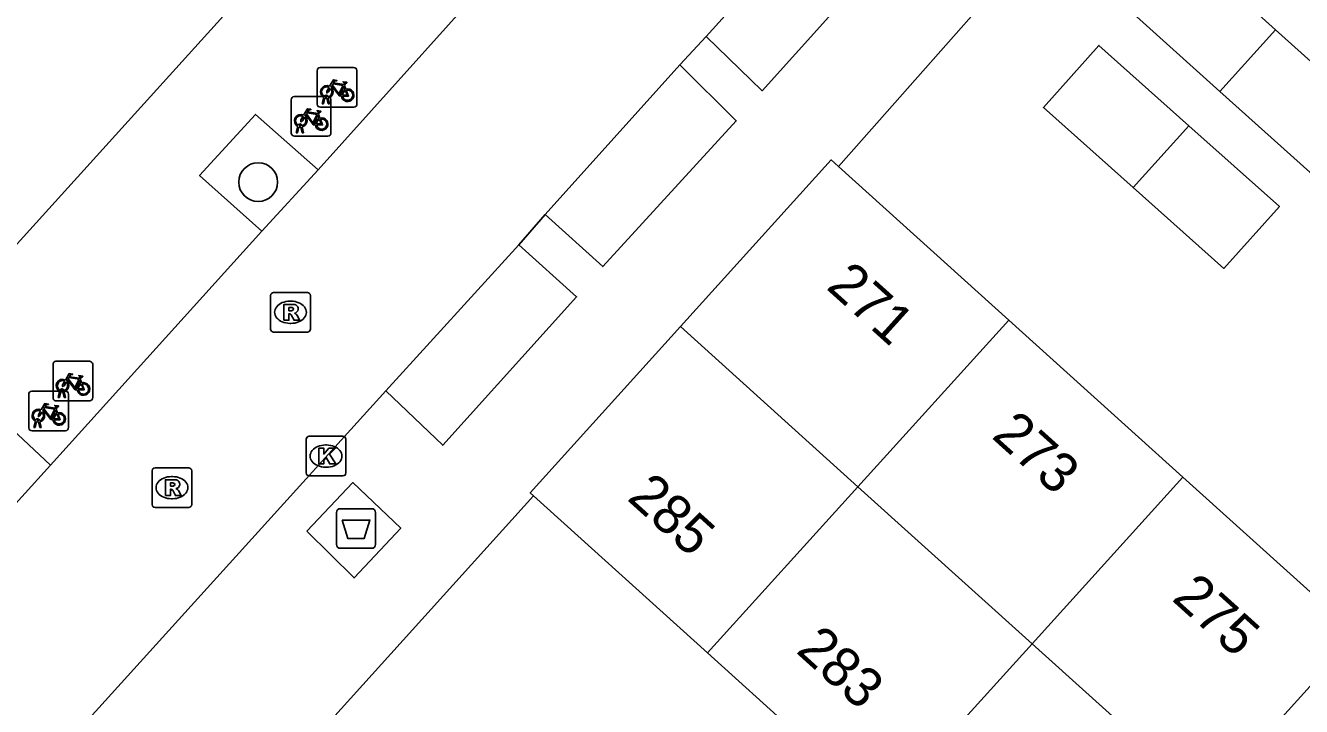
# Model space of a CAD drawing. Extents: x 161772 to 163123, y 383092 to 383917.
# Drawn here: x 162073.6 to 162105.76, y 383195.91 to 383213.09 of the extents above; entities that cross this region are included whole.
import ezdxf

# ---------------------------------------------------------------- set-up
doc = ezdxf.new("R2010")
doc.units = 0
for name, color, linetype in [('IMGEO_Afval_apart_plaats', 7, 'Continuous'), ('IMGEO_Boom', 7, 'Continuous'), ('IMGEO_Fietsenrek', 7, 'Continuous'), ('IMGEO_Kolk', 7, 'Continuous'), ('IMGEO_Pand', 7, 'Continuous'), ('IMGEO_Pand_nummerreeks', 7, 'Continuous'), ('IMGEO_Rijbaan_lokaal_open', 7, 'Continuous'), ('IMGEO_Rioolput', 7, 'Continuous'), ('IMGEO_Voetpad_gesloten', 7, 'Continuous'), ('IMGEO_Voetpad_open', 7, 'Continuous')]:
    doc.layers.add(name, color=color, linetype=linetype)

msp = doc.modelspace()

# ---------------------------------------------------------------- linework, layer by layer
at = {"layer": 'IMGEO_Afval_apart_plaats'}
for p, q in [((162081.531, 383200.9), (162082.321, 383200.9)), ((162082.321, 383200.9), (162081.531, 383200.9)), ((162081.431, 383200), (162081.431, 383200.8)), ((162081.431, 383200.8), (162081.431, 383200)), ((162082.421, 383200.8), (162082.421, 383200)), ((162082.421, 383200), (162082.421, 383200.8)), ((162082.321, 383199.9), (162081.531, 383199.9)), ((162081.531, 383199.9), (162082.321, 383199.9))]:
    msp.add_line(p, q, dxfattribs=at)
msp.add_lwpolyline([(162081.574, 383200.614), (162082.278, 383200.614), (162082.129, 383200.144), (162081.723, 383200.144), (162081.574, 383200.614)], dxfattribs=at)
for centre, start, end in [((162081.531, 383200.8), 90, 180), ((162081.531, 383200.8), 90, 180), ((162082.321, 383200.8), 0, 90), ((162082.321, 383200.8), 360, 90), ((162081.531, 383200), 180, 270), ((162081.531, 383200), 180, 270), ((162082.321, 383200), 270, 0), ((162082.321, 383200), 270, 0)]:
    msp.add_arc(centre, 0.1, start, end, dxfattribs=at)
at = {"layer": 'IMGEO_Boom'}
msp.add_circle((162079.461, 383209.138), 0.489, dxfattribs=at)
at = {"layer": 'IMGEO_Fietsenrek'}
for p, q in [((162080.948, 383211.104), (162080.948, 383211.945)), ((162080.948, 383211.945), (162080.948, 383211.104)), ((162081.023, 383212.029), (162081.864, 383212.029)), ((162081.864, 383212.029), (162081.023, 383212.029)), ((162081.948, 383211.954), (162081.948, 383211.113)), ((162081.948, 383211.113), (162081.948, 383211.954)), ((162081.635, 383211.578), (162081.671, 383211.483)), ((162080.293, 383210.375), (162080.293, 383211.216)), ((162080.293, 383211.216), (162080.293, 383210.375)), ((162080.368, 383211.3), (162081.209, 383211.3)), ((162081.209, 383211.3), (162080.368, 383211.3)), ((162081.075, 383211.113), (162081.114, 383211.273)), ((162081.109, 383211.113), (162081.075, 383211.113)), ((162081.144, 383211.261), (162081.109, 383211.113)), ((162081.186, 383211.285), (162081.185, 383211.289)), ((162081.227, 383211.113), (162081.193, 383211.255)), ((162081.217, 383211.296), (162081.218, 383211.289)), ((162081.225, 383211.259), (162081.26, 383211.113)), ((162081.26, 383211.113), (162081.227, 383211.113)), ((162081.293, 383211.225), (162081.293, 383210.384)), ((162081.293, 383210.384), (162081.293, 383211.225)), ((162080.98, 383210.849), (162081.016, 383210.754)), ((162081.873, 383211.029), (162081.032, 383211.029)), ((162081.032, 383211.029), (162081.873, 383211.029)), ((162080.42, 383210.384), (162080.459, 383210.544)), ((162080.489, 383210.532), (162080.454, 383210.384)), ((162080.531, 383210.556), (162080.53, 383210.56)), ((162080.572, 383210.384), (162080.538, 383210.526)), ((162080.562, 383210.567), (162080.563, 383210.56)), ((162080.57, 383210.53), (162080.605, 383210.384)), ((162081.218, 383210.3), (162080.377, 383210.3)), ((162080.377, 383210.3), (162081.218, 383210.3)), ((162080.454, 383210.384), (162080.42, 383210.384)), ((162080.605, 383210.384), (162080.572, 383210.384)), ((162074.289, 383203.694), (162074.289, 383204.535)), ((162074.289, 383204.535), (162074.289, 383203.694)), ((162074.364, 383204.619), (162075.205, 383204.619)), ((162075.205, 383204.619), (162074.364, 383204.619)), ((162075.289, 383204.544), (162075.289, 383203.703)), ((162075.289, 383203.703), (162075.289, 383204.544)), ((162074.976, 383204.168), (162075.012, 383204.073)), ((162073.678, 383202.939), (162073.678, 383203.78)), ((162073.678, 383203.78), (162073.678, 383202.939)), ((162073.753, 383203.864), (162074.594, 383203.864)), ((162074.594, 383203.864), (162073.753, 383203.864)), ((162074.416, 383203.703), (162074.455, 383203.863)), ((162074.45, 383203.703), (162074.416, 383203.703)), ((162074.485, 383203.851), (162074.45, 383203.703)), ((162074.527, 383203.875), (162074.526, 383203.879)), ((162074.568, 383203.703), (162074.534, 383203.845)), ((162074.558, 383203.886), (162074.559, 383203.879)), ((162074.566, 383203.849), (162074.601, 383203.703)), ((162074.601, 383203.703), (162074.568, 383203.703)), ((162074.678, 383203.789), (162074.678, 383202.948)), ((162074.678, 383202.948), (162074.678, 383203.789)), ((162074.365, 383203.413), (162074.401, 383203.318)), ((162075.214, 383203.619), (162074.373, 383203.619)), ((162074.373, 383203.619), (162075.214, 383203.619)), ((162073.805, 383202.948), (162073.844, 383203.108)), ((162073.874, 383203.096), (162073.839, 383202.948)), ((162073.916, 383203.12), (162073.915, 383203.124)), ((162073.957, 383202.948), (162073.923, 383203.09)), ((162073.947, 383203.131), (162073.948, 383203.124)), ((162073.955, 383203.094), (162073.99, 383202.948)), ((162074.603, 383202.864), (162073.762, 383202.864)), ((162073.762, 383202.864), (162074.603, 383202.864)), ((162073.839, 383202.948), (162073.805, 383202.948)), ((162073.99, 383202.948), (162073.957, 383202.948))]:
    msp.add_line(p, q, dxfattribs=at)
for points in [[(162081.282, 383211.503), (162081.23, 383211.413), (162081.19, 383211.388), (162081.191, 383211.435), (162081.246, 383211.529)], [(162081.261, 383211.555), (162081.356, 383211.719), (162081.442, 383211.705), (162081.444, 383211.696), (162081.388, 383211.685), (162081.361, 383211.64), (162081.617, 383211.599)], [(162081.557, 383211.311), (162081.507, 383211.311), (162081.316, 383211.562), (162081.297, 383211.53)], [(162081.604, 383211.574), (162081.347, 383211.615), (162081.33, 383211.586), (162081.497, 383211.366), (162081.604, 383211.574)], [(162081.652, 383211.476), (162081.622, 383211.553), (162081.513, 383211.335), (162081.556, 383211.335)], [(162081.586, 383211.335), (162081.706, 383211.334), (162081.662, 383211.448)], [(162081.682, 383211.455), (162081.737, 383211.31), (162081.587, 383211.31)], [(162081.617, 383211.599), (162081.642, 383211.648), (162081.636, 383211.652), (162081.613, 383211.656), (162081.601, 383211.663), (162081.6, 383211.666), (162081.602, 383211.671), (162081.697, 383211.656), (162081.699, 383211.646), (162081.689, 383211.633), (162081.677, 383211.627), (162081.663, 383211.633), (162081.635, 383211.578)], [(162080.627, 383210.774), (162080.575, 383210.684), (162080.535, 383210.659), (162080.536, 383210.706), (162080.591, 383210.8)], [(162080.606, 383210.826), (162080.701, 383210.99), (162080.787, 383210.976), (162080.789, 383210.967), (162080.733, 383210.956), (162080.706, 383210.911), (162080.962, 383210.87)], [(162080.902, 383210.582), (162080.852, 383210.582), (162080.661, 383210.833), (162080.642, 383210.801)], [(162080.949, 383210.845), (162080.692, 383210.886), (162080.675, 383210.857), (162080.842, 383210.637), (162080.949, 383210.845)], [(162080.997, 383210.747), (162080.967, 383210.824), (162080.858, 383210.606), (162080.901, 383210.606)], [(162080.962, 383210.87), (162080.987, 383210.919), (162080.981, 383210.923), (162080.958, 383210.927), (162080.946, 383210.934), (162080.945, 383210.937), (162080.947, 383210.942), (162081.042, 383210.927), (162081.044, 383210.917), (162081.034, 383210.904), (162081.022, 383210.898), (162081.008, 383210.904), (162080.98, 383210.849)], [(162080.931, 383210.606), (162081.051, 383210.605), (162081.007, 383210.719)], [(162081.027, 383210.726), (162081.082, 383210.581), (162080.932, 383210.581)], [(162074.623, 383204.093), (162074.571, 383204.003), (162074.531, 383203.978), (162074.532, 383204.025), (162074.587, 383204.119)], [(162074.602, 383204.145), (162074.697, 383204.309), (162074.783, 383204.295), (162074.785, 383204.286), (162074.729, 383204.275), (162074.702, 383204.23), (162074.958, 383204.189)], [(162074.898, 383203.901), (162074.848, 383203.901), (162074.657, 383204.152), (162074.638, 383204.12)], [(162074.945, 383204.164), (162074.688, 383204.205), (162074.671, 383204.176), (162074.838, 383203.956), (162074.945, 383204.164)], [(162074.993, 383204.066), (162074.963, 383204.143), (162074.854, 383203.925), (162074.897, 383203.925)], [(162074.927, 383203.925), (162075.047, 383203.924), (162075.003, 383204.038)], [(162075.023, 383204.045), (162075.078, 383203.9), (162074.928, 383203.9)], [(162074.958, 383204.189), (162074.983, 383204.238), (162074.977, 383204.242), (162074.954, 383204.246), (162074.942, 383204.253), (162074.941, 383204.256), (162074.943, 383204.261), (162075.038, 383204.246), (162075.04, 383204.236), (162075.03, 383204.223), (162075.018, 383204.217), (162075.004, 383204.223), (162074.976, 383204.168)], [(162073.991, 383203.39), (162074.086, 383203.554), (162074.172, 383203.54), (162074.174, 383203.531), (162074.118, 383203.52), (162074.091, 383203.475), (162074.347, 383203.434)], [(162074.287, 383203.146), (162074.237, 383203.146), (162074.046, 383203.397), (162074.027, 383203.365)], [(162074.334, 383203.409), (162074.077, 383203.45), (162074.06, 383203.421), (162074.227, 383203.201), (162074.334, 383203.409)], [(162074.382, 383203.311), (162074.352, 383203.388), (162074.243, 383203.17), (162074.286, 383203.17)], [(162074.347, 383203.434), (162074.372, 383203.483), (162074.366, 383203.487), (162074.343, 383203.491), (162074.331, 383203.498), (162074.33, 383203.501), (162074.332, 383203.506), (162074.427, 383203.491), (162074.429, 383203.481), (162074.419, 383203.468), (162074.407, 383203.462), (162074.393, 383203.468), (162074.365, 383203.413)], [(162074.012, 383203.338), (162073.96, 383203.248), (162073.92, 383203.223), (162073.921, 383203.27), (162073.976, 383203.364)], [(162074.316, 383203.17), (162074.436, 383203.169), (162074.392, 383203.283)], [(162074.412, 383203.29), (162074.467, 383203.145), (162074.317, 383203.145)]]:
    msp.add_lwpolyline(points, dxfattribs=at)
for centre, radius, start, end in [((162081.026, 383211.951), 0.0779, 92.4484, 184.2845), ((162081.026, 383211.951), 0.0779, 92.4484, 184.2845), ((162081.87, 383211.951), 0.0779, 2.4484, 94.2845), ((162081.87, 383211.951), 0.0779, 2.4484, 94.2845), ((162081.188, 383211.414), 0.159, 62.6766, 242.1369), ((162081.188, 383211.414), 0.129, 63.3192, 238.903), ((162081.188, 383211.414), 0.129, 283.6043, 43.4302), ((162081.188, 383211.414), 0.159, 283.5766, 46.6042), ((162081.715, 383211.33), 0.159, 113.3408, 178.3217), ((162081.715, 383211.33), 0.159, 187.0065, 105.7708), ((162081.715, 383211.33), 0.129, 113.923, 177.9556), ((162081.715, 383211.33), 0.129, 188.6715, 104.5883), ((162080.371, 383211.222), 0.0779, 92.4484, 184.2845), ((162080.371, 383211.222), 0.0779, 92.4484, 184.2845), ((162081.026, 383211.107), 0.0779, 182.4484, 274.2845), ((162081.026, 383211.107), 0.0779, 182.4484, 274.2845), ((162081.168, 383211.285), 0.0499, 12.8025, 158.6934), ((162081.188, 383211.414), 0.159, 253.9967, 271.7867), ((162081.168, 383211.285), 0.0174, 12.8025, 163.4502), ((162081.188, 383211.414), 0.129, 253.415, 269.0204), ((162081.215, 383211.222), 0.0779, 2.4484, 94.2845), ((162081.215, 383211.222), 0.0779, 2.4484, 94.2845), ((162081.87, 383211.107), 0.0779, 272.4484, 4.2845), ((162081.87, 383211.107), 0.0779, 272.4484, 4.2845), ((162080.533, 383210.685), 0.159, 62.6766, 242.1369), ((162080.533, 383210.685), 0.129, 63.3192, 238.903), ((162080.533, 383210.685), 0.129, 283.6043, 43.4302), ((162080.533, 383210.685), 0.159, 283.5766, 46.6042), ((162080.513, 383210.556), 0.0499, 12.8025, 158.6934), ((162080.533, 383210.685), 0.159, 253.9967, 271.7867), ((162080.513, 383210.556), 0.0174, 12.8025, 163.4502), ((162080.533, 383210.685), 0.129, 253.415, 269.0204), ((162081.06, 383210.601), 0.159, 113.3408, 178.3217), ((162081.06, 383210.601), 0.159, 187.0065, 105.7708), ((162081.06, 383210.601), 0.129, 113.923, 177.9556), ((162081.06, 383210.601), 0.129, 188.6715, 104.5883), ((162080.371, 383210.378), 0.0779, 182.4484, 274.2845), ((162080.371, 383210.378), 0.0779, 182.4484, 274.2845), ((162081.215, 383210.378), 0.0779, 272.4484, 4.2845), ((162081.215, 383210.378), 0.0779, 272.4484, 4.2845), ((162074.367, 383204.541), 0.0779, 92.4484, 184.2845), ((162074.367, 383204.541), 0.0779, 92.4484, 184.2845), ((162075.211, 383204.541), 0.0779, 2.4484, 94.2845), ((162075.211, 383204.541), 0.0779, 2.4484, 94.2845), ((162074.529, 383204.004), 0.159, 62.6766, 242.1369), ((162074.529, 383204.004), 0.129, 63.3192, 238.903), ((162074.529, 383204.004), 0.129, 283.6043, 43.4302), ((162074.529, 383204.004), 0.159, 283.5766, 46.6042), ((162075.056, 383203.92), 0.159, 113.3408, 178.3217), ((162075.056, 383203.92), 0.159, 187.0065, 105.7708), ((162075.056, 383203.92), 0.129, 113.923, 177.9556), ((162075.056, 383203.92), 0.129, 188.6715, 104.5883), ((162073.756, 383203.786), 0.0779, 92.4484, 184.2845), ((162073.756, 383203.786), 0.0779, 92.4484, 184.2845), ((162074.509, 383203.875), 0.0499, 12.8025, 158.6934), ((162074.529, 383204.004), 0.159, 253.9967, 271.7867), ((162074.509, 383203.875), 0.0174, 12.8025, 163.4502), ((162074.529, 383204.004), 0.129, 253.415, 269.0204), ((162074.6, 383203.786), 0.0779, 2.4484, 94.2845), ((162074.6, 383203.786), 0.0779, 2.4484, 94.2845), ((162075.211, 383203.697), 0.0779, 272.4484, 4.2845), ((162075.211, 383203.697), 0.0779, 272.4484, 4.2845), ((162073.918, 383203.249), 0.159, 62.6766, 242.1369), ((162073.918, 383203.249), 0.129, 63.3192, 238.903), ((162074.367, 383203.697), 0.0779, 182.4484, 274.2845), ((162074.367, 383203.697), 0.0779, 182.4484, 274.2845), ((162073.898, 383203.12), 0.0499, 12.8025, 158.6934), ((162073.918, 383203.249), 0.159, 253.9967, 271.7867), ((162073.898, 383203.12), 0.0174, 12.8025, 163.4502), ((162073.918, 383203.249), 0.129, 253.415, 269.0204), ((162073.918, 383203.249), 0.129, 283.6043, 43.4302), ((162073.918, 383203.249), 0.159, 283.5766, 46.6042), ((162074.445, 383203.165), 0.159, 113.3408, 178.3217), ((162074.445, 383203.165), 0.159, 187.0065, 105.7708), ((162074.445, 383203.165), 0.129, 113.923, 177.9556), ((162074.445, 383203.165), 0.129, 188.6715, 104.5883), ((162073.756, 383202.942), 0.0779, 182.4484, 274.2845), ((162073.756, 383202.942), 0.0779, 182.4484, 274.2845), ((162074.6, 383202.942), 0.0779, 272.4484, 4.2845), ((162074.6, 383202.942), 0.0779, 272.4484, 4.2845)]:
    msp.add_arc(centre, radius, start, end, dxfattribs=at)
at = {"layer": 'IMGEO_Kolk'}
for p, q in [((162080.67, 383201.801), (162080.67, 383202.653)), ((162080.745, 383202.727), (162081.597, 383202.727)), ((162081.158, 383202.507), (162081.183, 383202.507)), ((162081.671, 383202.653), (162081.671, 383201.801)), ((162081.181, 383201.947), (162081.156, 383201.947)), ((162081.597, 383201.727), (162080.745, 383201.727))]:
    msp.add_line(p, q, dxfattribs=at)
for points in [[(162080.67, 383201.801), (162080.67, 383202.653)], [(162080.745, 383202.727), (162081.597, 383202.727)], [(162080.991, 383202.427), (162081.114, 383202.427), (162081.114, 383202.276), (162081.244, 383202.427), (162081.408, 383202.427), (162081.262, 383202.276), (162081.415, 383202.027), (162081.263, 383202.027), (162081.178, 383202.191), (162081.114, 383202.124), (162081.114, 383202.027), (162080.991, 383202.027), (162080.991, 383202.427)], [(162081.671, 383202.653), (162081.671, 383201.801)], [(162081.597, 383201.727), (162080.745, 383201.727)]]:
    msp.add_lwpolyline(points, dxfattribs=at)
for centre, start, end in [((162080.747, 383202.651), 91.552, 178.448), ((162080.747, 383202.651), 91.552, 178.448), ((162081.595, 383202.651), 1.552, 88.448), ((162081.595, 383202.651), 1.552, 88.448), ((162080.747, 383201.803), 181.552, 268.448), ((162080.747, 383201.803), 181.552, 268.448), ((162081.595, 383201.803), 271.552, 358.448), ((162081.595, 383201.803), 271.552, 358.448)]:
    msp.add_arc(centre, 0.0765, start, end, dxfattribs=at)
for centre, major_axis, ratio, start_param, end_param in [((162081.157, 383202.227), (-0.387, 0.002), 0.722429, 4.712389, 7.853982), ((162081.182, 383202.227), (-0.39, 0.002), 0.717154, 1.570796, 4.712389)]:
    msp.add_ellipse(centre, major_axis=major_axis, ratio=ratio, start_param=start_param, end_param=end_param, dxfattribs=at)
at = {"layer": 'IMGEO_Pand'}
for points in [[(162103.698, 383211.427), (162101.431, 383213.469), (162102.822, 383215.036), (162105.1, 383212.984)], [(162105.1, 383212.984), (162107.367, 383210.943), (162105.964, 383209.385), (162103.698, 383211.427)], [(162105.1, 383212.984), (162103.698, 383211.427)], [(162101.515, 383209.005), (162099.254, 383211.024), (162100.651, 383212.588), (162102.918, 383210.562)], [(162102.918, 383210.562), (162105.2, 383208.524), (162103.804, 383206.961), (162101.515, 383209.005)], [(162102.918, 383210.562), (162101.515, 383209.005)], [(162094.087, 383209.529), (162093.9, 383209.698), (162090.104, 383205.493)], [(162094.087, 383209.529), (162098.378, 383205.658)], [(162094.578, 383201.455), (162098.378, 383205.658)], [(162098.378, 383205.658), (162102.77, 383201.695)], [(162090.104, 383205.493), (162086.317, 383201.299), (162086.397, 383201.227)], [(162094.578, 383201.455), (162090.104, 383205.493)], [(162090.785, 383197.26), (162094.578, 383201.455)], [(162098.969, 383197.491), (162094.578, 383201.455)], [(162098.969, 383197.491), (162102.77, 383201.695)], [(162102.77, 383201.695), (162107.162, 383197.733)], [(162090.785, 383197.26), (162086.397, 383201.227)], [(162103.361, 383193.528), (162107.162, 383197.733)], [(162095.174, 383193.293), (162098.969, 383197.491)], [(162103.361, 383193.528), (162098.969, 383197.491)], [(162095.174, 383193.293), (162090.785, 383197.26)]]:
    msp.add_lwpolyline(points, dxfattribs=at)
at = {"layer": 'IMGEO_Rijbaan_lokaal_open'}
for points in [[(162068.652, 383202.355), (162096.663, 383233.336), (162100.456, 383238.097), (162111.993, 383252.292), (162112.228, 383252.578), (162118.339, 383260.004), (162114.439, 383263.213), (162114.338, 383263.296), (162092.847, 383280.981), (162088.992, 383283.992)], [(162090.753, 383212.81), (162094.09, 383216.514)], [(162086.275, 383215.36), (162080.969, 383209.451)], [(162090.088, 383212.094), (162090.753, 383212.81)], [(162086.694, 383208.318), (162090.088, 383212.094)], [(162079.552, 383207.898), (162077.982, 383209.307), (162079.394, 383210.845), (162080.969, 383209.451)], [(162080.969, 383209.451), (162079.552, 383207.898)], [(162086.03, 383207.558), (162086.694, 383208.318)], [(162079.552, 383207.898), (162074.229, 383201.995)], [(162082.677, 383203.875), (162086.03, 383207.558)], [(162059.513, 383178.276), (162082.677, 383203.875)], [(162072.856, 383200.493), (162071.275, 383201.86), (162072.708, 383203.421), (162074.229, 383201.995)], [(162074.229, 383201.995), (162072.856, 383200.493)]]:
    msp.add_lwpolyline(points, dxfattribs=at)
at = {"layer": 'IMGEO_Rioolput'}
for p, q in [((162079.774, 383205.428), (162079.774, 383206.28)), ((162079.849, 383206.354), (162080.701, 383206.354)), ((162080.775, 383206.28), (162080.775, 383205.428)), ((162080.262, 383206.134), (162080.287, 383206.134)), ((162080.701, 383205.354), (162079.849, 383205.354)), ((162080.285, 383205.574), (162080.26, 383205.574)), ((162076.786, 383201.004), (162076.786, 383201.856)), ((162076.861, 383201.93), (162077.713, 383201.93)), ((162077.787, 383201.856), (162077.787, 383201.004)), ((162077.274, 383201.71), (162077.299, 383201.71)), ((162077.297, 383201.15), (162077.272, 383201.15)), ((162077.713, 383200.93), (162076.861, 383200.93))]:
    msp.add_line(p, q, dxfattribs=at)
for points in [[(162079.774, 383205.428), (162079.774, 383206.28)], [(162079.849, 383206.354), (162080.701, 383206.354)], [(162080.775, 383206.28), (162080.775, 383205.428)], [(162080.363, 383206.052), (162080.111, 383206.054), (162080.111, 383205.654)], [(162080.289, 383205.973), (162080.235, 383205.973), (162080.235, 383205.892)], [(162080.111, 383205.654), (162080.235, 383205.654), (162080.235, 383205.816), (162080.246, 383205.816)], [(162080.235, 383205.892), (162080.287, 383205.892)], [(162080.293, 383205.787), (162080.364, 383205.654), (162080.504, 383205.654), (162080.439, 383205.78)], [(162080.701, 383205.354), (162079.849, 383205.354)], [(162076.786, 383201.004), (162076.786, 383201.856)], [(162076.861, 383201.93), (162077.713, 383201.93)], [(162077.787, 383201.856), (162077.787, 383201.004)], [(162077.375, 383201.628), (162077.123, 383201.63), (162077.123, 383201.23)], [(162077.301, 383201.549), (162077.247, 383201.549), (162077.247, 383201.468)], [(162077.247, 383201.468), (162077.299, 383201.468)], [(162077.123, 383201.23), (162077.247, 383201.23), (162077.247, 383201.392), (162077.258, 383201.392)], [(162077.305, 383201.363), (162077.376, 383201.23), (162077.516, 383201.23), (162077.451, 383201.356)], [(162077.713, 383200.93), (162076.861, 383200.93)]]:
    msp.add_lwpolyline(points, dxfattribs=at)
for centre, radius, start, end in [((162079.851, 383206.278), 0.0765, 91.552, 178.448), ((162079.851, 383206.278), 0.0765, 91.552, 178.448), ((162080.699, 383206.278), 0.0765, 1.552, 88.448), ((162080.699, 383206.278), 0.0765, 1.552, 88.448), ((162080.295, 383205.877), 0.0964, 77.0061, 93.1865), ((162080.309, 383205.934), 0.0378, 276.6634, 79.6772), ((162080.362, 383205.942), 0.109, 350.3612, 89.416), ((162080.245, 383205.763), 0.0533, 26.0293, 88.6989), ((162080.271, 383206.081), 0.19, 274.7715, 282.9687), ((162080.36, 383205.942), 0.112, 277.5842, 350.9817), ((162080.344, 383205.727), 0.108, 29.5134, 73.7905), ((162079.851, 383205.43), 0.0765, 181.552, 268.448), ((162079.851, 383205.43), 0.0765, 181.552, 268.448), ((162080.699, 383205.43), 0.0765, 271.552, 358.448), ((162080.699, 383205.43), 0.0765, 271.552, 358.448), ((162076.863, 383201.854), 0.0765, 91.552, 178.448), ((162076.863, 383201.854), 0.0765, 91.552, 178.448), ((162077.711, 383201.854), 0.0765, 1.552, 88.448), ((162077.711, 383201.854), 0.0765, 1.552, 88.448), ((162077.283, 383201.657), 0.19, 274.7715, 282.9687), ((162077.307, 383201.453), 0.0964, 77.0061, 93.1865), ((162077.321, 383201.51), 0.0378, 276.6634, 79.6772), ((162077.374, 383201.518), 0.109, 350.3612, 89.416), ((162077.372, 383201.518), 0.112, 277.5842, 350.9817), ((162077.257, 383201.339), 0.0533, 26.0293, 88.6989), ((162077.356, 383201.303), 0.108, 29.5134, 73.7905), ((162076.863, 383201.006), 0.0765, 181.552, 268.448), ((162076.863, 383201.006), 0.0765, 181.552, 268.448), ((162077.711, 383201.006), 0.0765, 271.552, 358.448), ((162077.711, 383201.006), 0.0765, 271.552, 358.448)]:
    msp.add_arc(centre, radius, start, end, dxfattribs=at)
for centre, major_axis, ratio, start_param, end_param in [((162080.261, 383205.854), (-0.387, 0.002), 0.722429, 4.712389, 7.853982), ((162080.286, 383205.854), (-0.39, 0.002), 0.717154, 1.570796, 4.712389), ((162077.273, 383201.43), (-0.387, 0.002), 0.722429, 4.712389, 7.853982), ((162077.298, 383201.43), (-0.39, 0.002), 0.717154, 1.570796, 4.712389)]:
    msp.add_ellipse(centre, major_axis=major_axis, ratio=ratio, start_param=start_param, end_param=end_param, dxfattribs=at)
at = {"layer": 'IMGEO_Voetpad_gesloten'}
msp.add_lwpolyline([(162080.689, 383200.336), (162081.876, 383199.154), (162083.052, 383200.407), (162081.848, 383201.56), (162080.689, 383200.336)], dxfattribs=at)
at = {"layer": 'IMGEO_Voetpad_open'}
for points in [[(162103.69, 383220.403), (162094.087, 383209.529)], [(162090.753, 383212.81), (162092.166, 383211.442), (162095.526, 383215.184), (162094.09, 383216.514)], [(162086.694, 383208.318), (162088.145, 383207.008), (162091.512, 383210.68), (162090.088, 383212.094)], [(162082.677, 383203.875), (162084.114, 383202.501), (162087.486, 383206.248), (162086.03, 383207.558)], [(162086.397, 383201.227), (162076.705, 383190.48)]]:
    msp.add_lwpolyline(points, dxfattribs=at)

# ---------------------------------------------------------------- texts
at = {"layer": 'IMGEO_Pand_nummerreeks'}
for s, rotation, p in [('271', 317.9449, (162093.752, 383206.464)), ('273', 317.9449, (162097.921, 383202.703)), ('285', 317.8819, (162088.732, 383201.138)), ('275', 317.9449, (162102.463, 383198.605)), ('283', 317.8819, (162092.991, 383197.287))]:
    msp.add_text(s, height=1, rotation=rotation, dxfattribs=at).set_placement(p)

doc.saveas('drawing.dxf')
